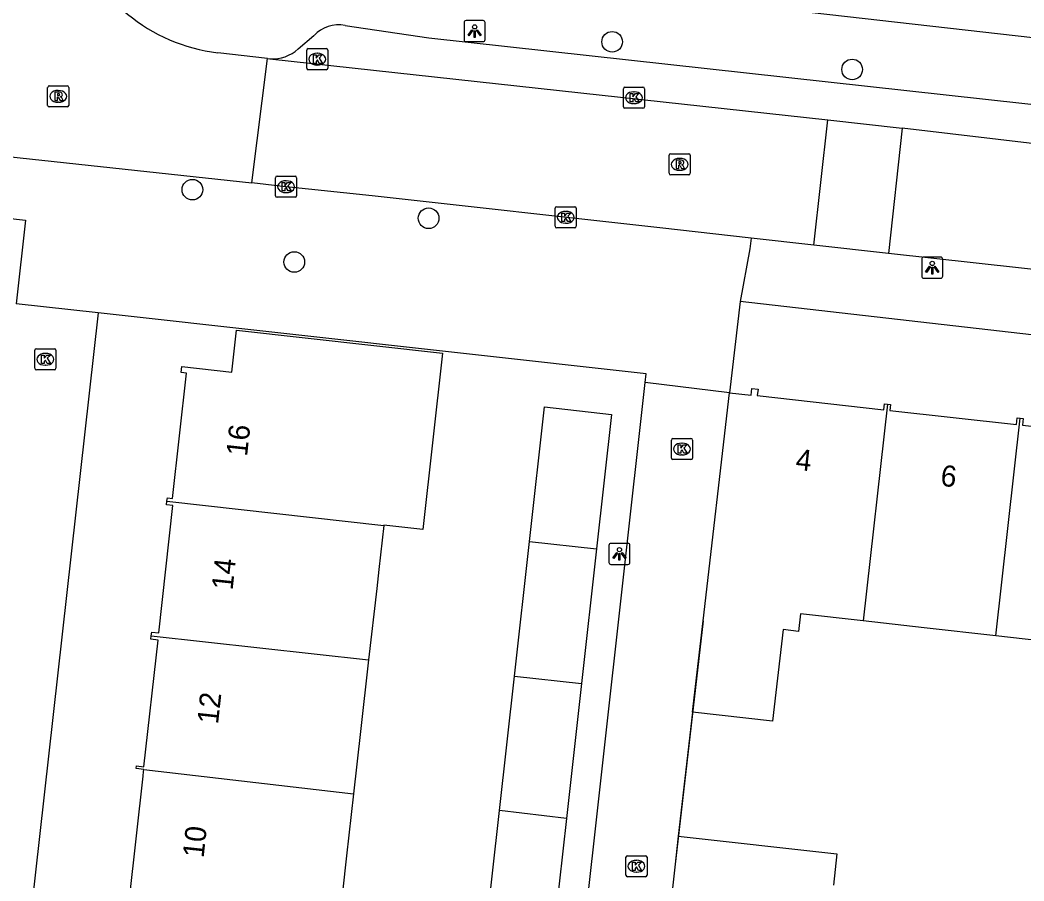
# Model space of a CAD drawing. Extents: x 162082 to 163393, y 388091 to 388632.
# Drawn here: x 163009.74 to 163057.31, y 388343.14 to 388383.95 of the extents above; entities that cross this region are included whole.
import ezdxf

# ---------------------------------------------------------------- set-up
doc = ezdxf.new("R2010")
doc.units = 0
for name, color, linetype in [('IMGEO_Boom', 7, 'Continuous'), ('IMGEO_Kolk', 7, 'Continuous'), ('IMGEO_Lichtpunt', 7, 'Continuous'), ('IMGEO_Muur', 7, 'Continuous'), ('IMGEO_Pand', 7, 'Continuous'), ('IMGEO_Pand_nummerreeks', 7, 'Continuous'), ('IMGEO_Rijbaan_lokaal_open', 7, 'Continuous'), ('IMGEO_Rioolput', 7, 'Continuous'), ('IMGEO_Voetpad_open', 7, 'Continuous')]:
    doc.layers.add(name, color=color, linetype=linetype)

msp = doc.modelspace()

# ---------------------------------------------------------------- linework, layer by layer
at = {"layer": 'IMGEO_Boom'}
for centre in [(163037.798, 388382.916), (163049.169, 388381.604), (163017.91, 388375.907), (163029.102, 388374.553), (163022.737, 388372.478)]:
    msp.add_circle(centre, 0.489, dxfattribs=at)
at = {"layer": 'IMGEO_Kolk'}
for p, q in [((163023.326, 388381.666), (163023.326, 388382.518)), ((163023.401, 388382.592), (163024.253, 388382.592)), ((163023.814, 388382.372), (163023.839, 388382.372)), ((163024.327, 388382.518), (163024.327, 388381.666)), ((163023.837, 388381.812), (163023.812, 388381.812)), ((163024.253, 388381.592), (163023.401, 388381.592)), ((163038.405, 388380.765), (163039.257, 388380.765)), ((163038.33, 388379.839), (163038.33, 388380.691)), ((163038.818, 388380.545), (163038.843, 388380.545)), ((163039.331, 388380.691), (163039.331, 388379.839)), ((163038.841, 388379.985), (163038.816, 388379.985)), ((163039.257, 388379.765), (163038.405, 388379.765)), ((163021.847, 388375.622), (163021.847, 388376.474)), ((163021.922, 388376.548), (163022.774, 388376.548)), ((163022.848, 388376.474), (163022.848, 388375.622)), ((163022.335, 388376.328), (163022.36, 388376.328)), ((163022.774, 388375.548), (163021.922, 388375.548)), ((163022.358, 388375.768), (163022.333, 388375.768)), ((163035.099, 388374.171), (163035.099, 388375.023)), ((163035.174, 388375.097), (163036.026, 388375.097)), ((163036.1, 388375.023), (163036.1, 388374.171)), ((163035.587, 388374.877), (163035.612, 388374.877)), ((163036.026, 388374.097), (163035.174, 388374.097)), ((163035.61, 388374.317), (163035.585, 388374.317)), ((163010.517, 388368.368), (163011.369, 388368.368)), ((163010.442, 388367.442), (163010.442, 388368.294)), ((163010.93, 388368.148), (163010.955, 388368.148)), ((163011.443, 388368.294), (163011.443, 388367.442)), ((163010.953, 388367.588), (163010.928, 388367.588)), ((163011.369, 388367.368), (163010.517, 388367.368)), ((163040.68, 388364.112), (163041.532, 388364.112)), ((163040.605, 388363.186), (163040.605, 388364.038)), ((163041.093, 388363.892), (163041.118, 388363.892)), ((163041.606, 388364.038), (163041.606, 388363.186)), ((163041.116, 388363.332), (163041.091, 388363.332)), ((163041.532, 388363.112), (163040.68, 388363.112)), ((163038.449, 388343.41), (163038.449, 388344.262)), ((163038.524, 388344.336), (163039.376, 388344.336)), ((163038.937, 388344.116), (163038.962, 388344.116)), ((163039.45, 388344.262), (163039.45, 388343.41)), ((163039.376, 388343.336), (163038.524, 388343.336)), ((163038.96, 388343.556), (163038.935, 388343.556))]:
    msp.add_line(p, q, dxfattribs=at)
for points in [[(163023.326, 388381.666), (163023.326, 388382.518)], [(163023.401, 388382.592), (163024.253, 388382.592)], [(163023.647, 388382.292), (163023.77, 388382.292), (163023.77, 388382.141), (163023.9, 388382.292), (163024.064, 388382.292), (163023.918, 388382.141), (163024.071, 388381.892), (163023.919, 388381.892), (163023.834, 388382.056), (163023.77, 388381.989), (163023.77, 388381.892), (163023.647, 388381.892), (163023.647, 388382.292)], [(163024.327, 388382.518), (163024.327, 388381.666)], [(163024.253, 388381.592), (163023.401, 388381.592)], [(163038.405, 388380.765), (163039.257, 388380.765)], [(163038.33, 388379.839), (163038.33, 388380.691)], [(163038.651, 388380.465), (163038.774, 388380.465), (163038.774, 388380.314), (163038.904, 388380.465), (163039.068, 388380.465), (163038.922, 388380.314), (163039.075, 388380.065), (163038.923, 388380.065), (163038.838, 388380.229), (163038.774, 388380.162), (163038.774, 388380.065), (163038.651, 388380.065), (163038.651, 388380.465)], [(163039.331, 388380.691), (163039.331, 388379.839)], [(163039.257, 388379.765), (163038.405, 388379.765)], [(163021.847, 388375.622), (163021.847, 388376.474)], [(163021.922, 388376.548), (163022.774, 388376.548)], [(163022.848, 388376.474), (163022.848, 388375.622)], [(163022.168, 388376.248), (163022.291, 388376.248), (163022.291, 388376.097), (163022.421, 388376.248), (163022.585, 388376.248), (163022.439, 388376.097), (163022.592, 388375.848), (163022.44, 388375.848), (163022.355, 388376.012), (163022.291, 388375.945), (163022.291, 388375.848), (163022.168, 388375.848), (163022.168, 388376.248)], [(163022.774, 388375.548), (163021.922, 388375.548)], [(163035.099, 388374.171), (163035.099, 388375.023)], [(163035.174, 388375.097), (163036.026, 388375.097)], [(163036.1, 388375.023), (163036.1, 388374.171)], [(163035.42, 388374.797), (163035.543, 388374.797), (163035.543, 388374.646), (163035.673, 388374.797), (163035.837, 388374.797), (163035.691, 388374.646), (163035.844, 388374.397), (163035.692, 388374.397), (163035.607, 388374.561), (163035.543, 388374.494), (163035.543, 388374.397), (163035.42, 388374.397), (163035.42, 388374.797)], [(163036.026, 388374.097), (163035.174, 388374.097)], [(163010.517, 388368.368), (163011.369, 388368.368)], [(163010.442, 388367.442), (163010.442, 388368.294)], [(163010.763, 388368.068), (163010.886, 388368.068), (163010.886, 388367.917), (163011.016, 388368.068), (163011.18, 388368.068), (163011.034, 388367.917), (163011.187, 388367.668), (163011.035, 388367.668), (163010.95, 388367.832), (163010.886, 388367.765), (163010.886, 388367.668), (163010.763, 388367.668), (163010.763, 388368.068)], [(163011.443, 388368.294), (163011.443, 388367.442)], [(163011.369, 388367.368), (163010.517, 388367.368)], [(163040.68, 388364.112), (163041.532, 388364.112)], [(163040.605, 388363.186), (163040.605, 388364.038)], [(163040.926, 388363.812), (163041.049, 388363.812), (163041.049, 388363.661), (163041.179, 388363.812), (163041.343, 388363.812), (163041.197, 388363.661), (163041.35, 388363.412), (163041.198, 388363.412), (163041.113, 388363.576), (163041.049, 388363.509), (163041.049, 388363.412), (163040.926, 388363.412), (163040.926, 388363.812)], [(163041.606, 388364.038), (163041.606, 388363.186)], [(163041.532, 388363.112), (163040.68, 388363.112)], [(163038.449, 388343.41), (163038.449, 388344.262)], [(163038.524, 388344.336), (163039.376, 388344.336)], [(163039.45, 388344.262), (163039.45, 388343.41)], [(163038.77, 388344.036), (163038.893, 388344.036), (163038.893, 388343.885), (163039.023, 388344.036), (163039.187, 388344.036), (163039.041, 388343.885), (163039.194, 388343.636), (163039.042, 388343.636), (163038.957, 388343.8), (163038.893, 388343.733), (163038.893, 388343.636), (163038.77, 388343.636), (163038.77, 388344.036)], [(163039.376, 388343.336), (163038.524, 388343.336)]]:
    msp.add_lwpolyline(points, dxfattribs=at)
for centre, start, end in [((163023.403, 388382.516), 91.552, 178.448), ((163023.403, 388382.516), 91.552, 178.448), ((163024.251, 388382.516), 1.552, 88.448), ((163024.251, 388382.516), 1.552, 88.448), ((163023.403, 388381.668), 181.552, 268.448), ((163023.403, 388381.668), 181.552, 268.448), ((163024.251, 388381.668), 271.552, 358.448), ((163024.251, 388381.668), 271.552, 358.448), ((163038.407, 388380.689), 91.552, 178.448), ((163038.407, 388380.689), 91.552, 178.448), ((163039.255, 388380.689), 1.552, 88.448), ((163039.255, 388380.689), 1.552, 88.448), ((163038.407, 388379.841), 181.552, 268.448), ((163038.407, 388379.841), 181.552, 268.448), ((163039.255, 388379.841), 271.552, 358.448), ((163039.255, 388379.841), 271.552, 358.448), ((163021.924, 388376.472), 91.552, 178.448), ((163021.924, 388376.472), 91.552, 178.448), ((163022.772, 388376.472), 1.552, 88.448), ((163022.772, 388376.472), 1.552, 88.448), ((163021.924, 388375.624), 181.552, 268.448), ((163021.924, 388375.624), 181.552, 268.448), ((163022.772, 388375.624), 271.552, 358.448), ((163022.772, 388375.624), 271.552, 358.448), ((163035.176, 388375.021), 91.552, 178.448), ((163035.176, 388375.021), 91.552, 178.448), ((163036.024, 388375.021), 1.552, 88.448), ((163036.024, 388375.021), 1.552, 88.448), ((163035.176, 388374.173), 181.552, 268.448), ((163035.176, 388374.173), 181.552, 268.448), ((163036.024, 388374.173), 271.552, 358.448), ((163036.024, 388374.173), 271.552, 358.448), ((163010.519, 388368.292), 91.552, 178.448), ((163010.519, 388368.292), 91.552, 178.448), ((163011.367, 388368.292), 1.552, 88.448), ((163011.367, 388368.292), 1.552, 88.448), ((163010.519, 388367.444), 181.552, 268.448), ((163010.519, 388367.444), 181.552, 268.448), ((163011.367, 388367.444), 271.552, 358.448), ((163011.367, 388367.444), 271.552, 358.448), ((163040.682, 388364.036), 91.552, 178.448), ((163040.682, 388364.036), 91.552, 178.448), ((163041.53, 388364.036), 1.552, 88.448), ((163041.53, 388364.036), 1.552, 88.448), ((163040.682, 388363.188), 181.552, 268.448), ((163040.682, 388363.188), 181.552, 268.448), ((163041.53, 388363.188), 271.552, 358.448), ((163041.53, 388363.188), 271.552, 358.448), ((163038.526, 388344.26), 91.552, 178.448), ((163038.526, 388344.26), 91.552, 178.448), ((163039.374, 388344.26), 1.552, 88.448), ((163039.374, 388344.26), 1.552, 88.448), ((163038.526, 388343.412), 181.552, 268.448), ((163038.526, 388343.412), 181.552, 268.448), ((163039.374, 388343.412), 271.552, 358.448), ((163039.374, 388343.412), 271.552, 358.448)]:
    msp.add_arc(centre, 0.0765, start, end, dxfattribs=at)
for centre, major_axis, ratio, start_param, end_param in [((163023.813, 388382.092), (-0.387, 0.002), 0.722429, 4.712389, 7.853982), ((163023.838, 388382.092), (-0.39, 0.002), 0.717154, 1.570796, 4.712389), ((163038.817, 388380.265), (-0.387, 0.002), 0.722429, 4.712389, 7.853982), ((163038.842, 388380.265), (-0.39, 0.002), 0.717154, 1.570796, 4.712389), ((163022.334, 388376.048), (-0.387, 0.002), 0.722429, 4.712389, 7.853982), ((163022.359, 388376.048), (-0.39, 0.002), 0.717154, 1.570796, 4.712389), ((163035.586, 388374.597), (-0.387, 0.002), 0.722429, 4.712389, 7.853982), ((163035.611, 388374.597), (-0.39, 0.002), 0.717154, 1.570796, 4.712389), ((163010.929, 388367.868), (-0.387, 0.002), 0.722429, 4.712389, 7.853982), ((163010.954, 388367.868), (-0.39, 0.002), 0.717154, 1.570796, 4.712389), ((163041.092, 388363.612), (-0.387, 0.002), 0.722429, 4.712389, 7.853982), ((163041.117, 388363.612), (-0.39, 0.002), 0.717154, 1.570796, 4.712389), ((163038.936, 388343.836), (-0.387, 0.002), 0.722429, 4.712389, 7.853982), ((163038.961, 388343.836), (-0.39, 0.002), 0.717154, 1.570796, 4.712389)]:
    msp.add_ellipse(centre, major_axis=major_axis, ratio=ratio, start_param=start_param, end_param=end_param, dxfattribs=at)
at = {"layer": 'IMGEO_Lichtpunt'}
for p, q in [((163030.782, 388383.826), (163030.782, 388383.019)), ((163030.782, 388383.826), (163030.782, 388383.019)), ((163031.684, 388383.921), (163030.876, 388383.921)), ((163031.684, 388383.921), (163030.876, 388383.921)), ((163031.778, 388383.019), (163031.778, 388383.826)), ((163031.778, 388383.019), (163031.778, 388383.826)), ((163030.876, 388382.925), (163031.684, 388382.925)), ((163030.876, 388382.925), (163031.684, 388382.925)), ((163053.369, 388372.708), (163052.561, 388372.708)), ((163053.369, 388372.708), (163052.561, 388372.708)), ((163052.467, 388372.613), (163052.467, 388371.806)), ((163052.467, 388372.613), (163052.467, 388371.806)), ((163053.463, 388371.806), (163053.463, 388372.613)), ((163053.463, 388371.806), (163053.463, 388372.613)), ((163052.561, 388371.712), (163053.369, 388371.712)), ((163052.561, 388371.712), (163053.369, 388371.712)), ((163037.646, 388359.047), (163037.646, 388358.24)), ((163037.646, 388359.047), (163037.646, 388358.24)), ((163038.548, 388359.142), (163037.74, 388359.142)), ((163038.548, 388359.142), (163037.74, 388359.142)), ((163038.642, 388358.24), (163038.642, 388359.047)), ((163038.642, 388358.24), (163038.642, 388359.047)), ((163037.74, 388358.146), (163038.548, 388358.146)), ((163037.74, 388358.146), (163038.548, 388358.146))]:
    msp.add_line(p, q, dxfattribs=at)
for points in [[(163031.156, 388383.49), (163031.195, 388383.462), (163031.007, 388383.2), (163030.969, 388383.227), (163031.156, 388383.49)], [(163031.258, 388383.442), (163031.305, 388383.442), (163031.305, 388383.12), (163031.258, 388383.12), (163031.258, 388383.442)], [(163031.368, 388383.462), (163031.406, 388383.489), (163031.593, 388383.227), (163031.554, 388383.199), (163031.368, 388383.462)], [(163052.841, 388372.277), (163052.88, 388372.249), (163052.692, 388371.987), (163052.654, 388372.014), (163052.841, 388372.277)], [(163052.943, 388372.229), (163052.99, 388372.229), (163052.99, 388371.907), (163052.943, 388371.907), (163052.943, 388372.229)], [(163053.053, 388372.249), (163053.091, 388372.276), (163053.278, 388372.014), (163053.239, 388371.986), (163053.053, 388372.249)], [(163038.02, 388358.711), (163038.059, 388358.683), (163037.871, 388358.421), (163037.833, 388358.448), (163038.02, 388358.711)], [(163038.122, 388358.663), (163038.169, 388358.663), (163038.169, 388358.341), (163038.122, 388358.341), (163038.122, 388358.663)], [(163038.232, 388358.683), (163038.27, 388358.71), (163038.457, 388358.448), (163038.418, 388358.42), (163038.232, 388358.683)]]:
    msp.add_lwpolyline(points, dxfattribs=at)
for centre in [(163031.281, 388383.624), (163052.966, 388372.411), (163038.145, 388358.845)]:
    msp.add_circle(centre, 0.0994, dxfattribs=at)
for centre, start, end in [((163030.876, 388383.826), 90, 180), ((163030.876, 388383.826), 90, 180), ((163031.684, 388383.826), 0, 90), ((163031.684, 388383.826), 0, 90), ((163030.876, 388383.019), 180, 270), ((163030.876, 388383.019), 180, 270), ((163031.684, 388383.019), 270, 0), ((163031.684, 388383.019), 270, 360), ((163052.561, 388372.613), 90, 180), ((163052.561, 388372.613), 90, 180), ((163053.369, 388372.613), 0, 90), ((163053.369, 388372.613), 0, 90), ((163052.561, 388371.806), 180, 270), ((163052.561, 388371.806), 180, 270), ((163053.369, 388371.806), 270, 0), ((163053.369, 388371.806), 270, 360), ((163037.74, 388359.047), 90, 180), ((163037.74, 388359.047), 90, 180), ((163038.548, 388359.047), 0, 90), ((163038.548, 388359.047), 0, 90), ((163037.74, 388358.24), 180, 270), ((163037.74, 388358.24), 180, 270), ((163038.548, 388358.24), 270, 0), ((163038.548, 388358.24), 270, 360)]:
    msp.add_arc(centre, 0.0946, start, end, dxfattribs=at)
at = {"layer": 'IMGEO_Muur'}
msp.add_lwpolyline([(163042.111, 388355.474), (163040.763, 388343.796)], dxfattribs=at)
at = {"layer": 'IMGEO_Pand'}
for points in [[(163016.703, 388361.135), (163016.722, 388361.299), (163016.968, 388361.272), (163017.629, 388367.212), (163017.379, 388367.24), (163017.411, 388367.525), (163019.775, 388367.262), (163019.997, 388369.25), (163029.756, 388368.163), (163028.825, 388359.801), (163026.98, 388360.006), (163026.979, 388359.994)], [(163043.358, 388366.272), (163044.389, 388366.159), (163044.425, 388366.477), (163044.71, 388366.446), (163044.677, 388366.149), (163050.676, 388365.478), (163050.707, 388365.758), (163050.85, 388365.742)], [(163041.611, 388351.146), (163042.111, 388355.474), (163043.358, 388366.272)], [(163033.877, 388359.228), (163034.586, 388365.609), (163037.764, 388365.256), (163037.055, 388358.875)], [(163050.85, 388365.742), (163049.692, 388355.461)], [(163050.85, 388365.742), (163050.993, 388365.726), (163050.962, 388365.445), (163056.958, 388364.774), (163056.993, 388365.091), (163057.135, 388365.076)], [(163055.973, 388354.753), (163057.135, 388365.076)], [(163057.135, 388365.076), (163057.277, 388365.06), (163057.241, 388364.741), (163063.286, 388364.065), (163063.318, 388364.35), (163063.462, 388364.334)], [(163015.961, 388354.762), (163015.98, 388354.931), (163016.314, 388354.894), (163016.986, 388360.937), (163016.685, 388360.971), (163016.703, 388361.135)], [(163016.703, 388361.135), (163026.979, 388359.994)], [(163026.979, 388359.994), (163026.746, 388357.899), (163026.645, 388356.994), (163026.259, 388353.619)], [(163033.169, 388352.852), (163033.877, 388359.228)], [(163033.877, 388359.228), (163037.055, 388358.875)], [(163037.055, 388358.875), (163036.347, 388352.499)], [(163049.692, 388355.461), (163046.728, 388355.793), (163046.633, 388354.969), (163045.9, 388355.051), (163045.398, 388350.709), (163041.611, 388351.146)], [(163055.973, 388354.753), (163052.591, 388355.136), (163049.692, 388355.461)], [(163015.606, 388348.419), (163015.239, 388348.461), (163015.254, 388348.593), (163015.614, 388348.553), (163016.282, 388354.555), (163015.942, 388354.593), (163015.961, 388354.762)], [(163015.961, 388354.762), (163026.259, 388353.619)], [(163062.302, 388354.04), (163059.452, 388354.359), (163055.973, 388354.753)], [(163026.259, 388353.619), (163025.87, 388350.215), (163025.543, 388347.271)], [(163032.46, 388346.472), (163033.169, 388352.852)], [(163033.169, 388352.852), (163036.347, 388352.499)], [(163036.347, 388352.499), (163035.636, 388346.105)], [(163014.546, 388342.168), (163014.565, 388342.339), (163014.926, 388342.299), (163015.571, 388348.1), (163015.596, 388348.325), (163015.606, 388348.419)], [(163015.606, 388348.419), (163025.543, 388347.271)], [(163025.543, 388347.271), (163025.215, 388344.324), (163024.855, 388341.024)], [(163031.769, 388340.257), (163032.46, 388346.472)], [(163035.636, 388346.105), (163032.46, 388346.472)], [(163035.636, 388346.105), (163034.948, 388339.904)], [(163040.927, 388345.269), (163040.763, 388343.796), (163040.13, 388338.099), (163047.64, 388337.247)], [(163040.927, 388345.269), (163048.449, 388344.421), (163048.282, 388342.943)]]:
    msp.add_lwpolyline(points, dxfattribs=at)
at = {"layer": 'IMGEO_Rijbaan_lokaal_open'}
for points in [[(163021.473, 388382.126), (163019.11, 388382.395)], [(163020.733, 388376.234), (163021.473, 388382.126)], [(163021.473, 388382.126), (163021.586, 388382.114)], [(163021.586, 388382.114), (163048.015, 388379.213)], [(162984.268, 388380.165), (163020.733, 388376.234)], [(163047.36, 388373.275), (163048.015, 388379.213)], [(163048.015, 388379.213), (163051.544, 388378.826)], [(163051.544, 388378.826), (163050.888, 388372.886)], [(163110.336, 388372.094), (163071.745, 388376.443), (163051.544, 388378.826)], [(163044.378, 388373.604), (163040.062, 388374.092), (163026.424, 388375.608), (163022.055, 388376.08), (163020.733, 388376.234)], [(163047.36, 388373.275), (163044.378, 388373.604)], [(163050.888, 388372.886), (163047.36, 388373.275)], [(163109.621, 388366.406), (163050.888, 388372.886)], [(163035.331, 388330.563), (163039.363, 388366.766)], [(163043.358, 388366.272), (163039.363, 388366.766)], [(163041.611, 388351.146), (163040.927, 388345.269)]]:
    msp.add_lwpolyline(points, dxfattribs=at)
msp.add_arc((163020.12, 388390.646), 8.313, 198.0479, 263.0212, dxfattribs=at)
at = {"layer": 'IMGEO_Rioolput'}
for p, q in [((163011.051, 388379.904), (163011.051, 388380.756)), ((163011.126, 388380.83), (163011.978, 388380.83)), ((163012.052, 388380.756), (163012.052, 388379.904)), ((163011.539, 388380.61), (163011.564, 388380.61)), ((163011.978, 388379.83), (163011.126, 388379.83)), ((163011.562, 388380.05), (163011.537, 388380.05)), ((163040.499, 388376.683), (163040.499, 388377.535)), ((163040.574, 388377.609), (163041.426, 388377.609)), ((163041.5, 388377.535), (163041.5, 388376.683)), ((163040.987, 388377.389), (163041.012, 388377.389)), ((163041.426, 388376.609), (163040.574, 388376.609)), ((163041.01, 388376.829), (163040.985, 388376.829))]:
    msp.add_line(p, q, dxfattribs=at)
for points in [[(163011.051, 388379.904), (163011.051, 388380.756)], [(163011.126, 388380.83), (163011.978, 388380.83)], [(163012.052, 388380.756), (163012.052, 388379.904)], [(163011.64, 388380.528), (163011.388, 388380.53), (163011.388, 388380.13)], [(163011.388, 388380.13), (163011.512, 388380.13), (163011.512, 388380.292), (163011.523, 388380.292)], [(163011.566, 388380.449), (163011.512, 388380.449), (163011.512, 388380.368)], [(163011.512, 388380.368), (163011.564, 388380.368)], [(163011.57, 388380.263), (163011.641, 388380.13), (163011.781, 388380.13), (163011.716, 388380.256)], [(163011.978, 388379.83), (163011.126, 388379.83)], [(163040.499, 388376.683), (163040.499, 388377.535)], [(163040.574, 388377.609), (163041.426, 388377.609)], [(163041.5, 388377.535), (163041.5, 388376.683)], [(163041.088, 388377.307), (163040.836, 388377.309), (163040.836, 388376.909)], [(163040.836, 388376.909), (163040.96, 388376.909), (163040.96, 388377.071), (163040.971, 388377.071)], [(163041.014, 388377.228), (163040.96, 388377.228), (163040.96, 388377.147)], [(163040.96, 388377.147), (163041.012, 388377.147)], [(163041.018, 388377.042), (163041.089, 388376.909), (163041.229, 388376.909), (163041.164, 388377.035)], [(163041.426, 388376.609), (163040.574, 388376.609)]]:
    msp.add_lwpolyline(points, dxfattribs=at)
for centre, radius, start, end in [((163011.128, 388380.754), 0.0765, 91.552, 178.448), ((163011.128, 388380.754), 0.0765, 91.552, 178.448), ((163011.976, 388380.754), 0.0765, 1.552, 88.448), ((163011.976, 388380.754), 0.0765, 1.552, 88.448), ((163011.522, 388380.239), 0.0533, 26.0293, 88.6989), ((163011.548, 388380.557), 0.19, 274.7715, 282.9687), ((163011.572, 388380.353), 0.0964, 77.0061, 93.1865), ((163011.586, 388380.41), 0.0378, 276.6634, 79.6772), ((163011.639, 388380.418), 0.109, 350.3612, 89.416), ((163011.637, 388380.418), 0.112, 277.5842, 350.9817), ((163011.621, 388380.203), 0.108, 29.5134, 73.7905), ((163011.128, 388379.906), 0.0765, 181.552, 268.448), ((163011.128, 388379.906), 0.0765, 181.552, 268.448), ((163011.976, 388379.906), 0.0765, 271.552, 358.448), ((163011.976, 388379.906), 0.0765, 271.552, 358.448), ((163040.576, 388377.533), 0.0765, 91.552, 178.448), ((163040.576, 388377.533), 0.0765, 91.552, 178.448), ((163041.424, 388377.533), 0.0765, 1.552, 88.448), ((163041.424, 388377.533), 0.0765, 1.552, 88.448), ((163040.97, 388377.018), 0.0533, 26.0293, 88.6989), ((163040.996, 388377.336), 0.19, 274.7715, 282.9687), ((163041.02, 388377.132), 0.0964, 77.0061, 93.1865), ((163041.034, 388377.189), 0.0378, 276.6634, 79.6772), ((163041.087, 388377.197), 0.109, 350.3612, 89.416), ((163041.085, 388377.197), 0.112, 277.5842, 350.9817), ((163041.069, 388376.982), 0.108, 29.5134, 73.7905), ((163040.576, 388376.685), 0.0765, 181.552, 268.448), ((163040.576, 388376.685), 0.0765, 181.552, 268.448), ((163041.424, 388376.685), 0.0765, 271.552, 358.448), ((163041.424, 388376.685), 0.0765, 271.552, 358.448)]:
    msp.add_arc(centre, radius, start, end, dxfattribs=at)
for centre, major_axis, ratio, start_param, end_param in [((163011.538, 388380.33), (-0.387, 0.002), 0.722429, 4.712389, 7.853982), ((163011.563, 388380.33), (-0.39, 0.002), 0.717154, 1.570796, 4.712389), ((163040.986, 388377.109), (-0.387, 0.002), 0.722429, 4.712389, 7.853982), ((163041.011, 388377.109), (-0.39, 0.002), 0.717154, 1.570796, 4.712389)]:
    msp.add_ellipse(centre, major_axis=major_axis, ratio=ratio, start_param=start_param, end_param=end_param, dxfattribs=at)
at = {"layer": 'IMGEO_Voetpad_open'}
for points in [[(163097.61, 388378.592), (163017.997, 388387.624)], [(163025.141, 388383.695), (163029.112, 388383.106), (163097.053, 388375.608), (163101.638, 388375.101), (163110.59, 388374.111)], [(163022.922, 388382.58), (163023.671, 388383.215)], [(162966.913, 388379.037), (162986.604, 388377.09), (163000.604, 388375.516), (163010.001, 388374.46), (163009.556, 388370.497)], [(163044.378, 388373.604), (163044.321, 388373.109), (163043.859, 388370.607)], [(163013.441, 388370.076), (163009.556, 388370.497)], [(163043.859, 388370.607), (163043.358, 388366.272)], [(163147.342, 388359.113), (163134.198, 388360.66), (163120.564, 388362.251), (163088.73, 388365.476), (163043.859, 388370.607)], [(163013.441, 388370.076), (163002.97, 388276.7)], [(163039.363, 388366.766), (163039.409, 388367.179), (163013.441, 388370.076)]]:
    msp.add_lwpolyline(points, dxfattribs=at)
for centre, radius, start, end in [((163024.85, 388382.096), 1.625, 79.6696, 136.4973), ((163021.723, 388383.87), 1.761, 265.5468, 312.911)]:
    msp.add_arc(centre, radius, start, end, dxfattribs=at)

# ---------------------------------------------------------------- texts
at = {"layer": 'IMGEO_Pand_nummerreeks'}
for s, rotation, p in [('16', 83.8237, (163020.498, 388363.24)), ('4', 353.8063, (163046.461, 388362.636)), ('6', 353.5819, (163053.324, 388361.878)), ('14', 83.821, (163019.811, 388356.894)), ('12', 83.8237, (163019.124, 388350.544)), ('10', 83.8237, (163018.438, 388344.204))]:
    msp.add_text(s, height=1, rotation=rotation, dxfattribs=at).set_placement(p)

doc.saveas('drawing.dxf')
